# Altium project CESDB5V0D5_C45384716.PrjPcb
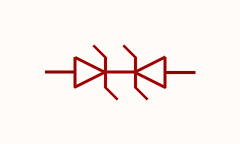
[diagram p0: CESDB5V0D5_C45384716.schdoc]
1 sheet, 1 parts. Net scope: global (net labels, ports and power ports of the same name join across sheets).

## Sheet CESDB5V0D5_C45384716.schdoc
size 127 x 101 mm

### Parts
D?  cesdb5v0d5_c45384716  [SOD-523_L1.2-W0.8-LS1.6-BI-1]  (value not drawn)

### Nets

Not connected (* = marked no-connect by the designer): D? 1 2

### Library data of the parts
D? = cesdb5v0d5_c45384716: 极性:双向;反向截止电压(Vrwm):5V;钳位电压:16V;峰值脉冲电流(Ipp):7A@8/20us;峰值脉冲功率(Ppp):100W@8/20us;击穿电压(VBR):8V;; Manufacturer: JSMSEMI(杰盛微); AddInBom: yes; ModelId: 1c16aded1c9949d28765d4c5d55c2785; ModelTransform: 62.992,31.496,0,0,0,0,0,0,0; Polarity: 双向; Reverse Stand-Off Voltage (Vrwm): 5V; Clamping Voltage: 16V; Voltage - Breakdown: 8V; Reverse Leakage Current (Ir): 51uA; Number of Channels: 单路; level of protection: IEC 61000-4-2; Type: TVS; Junction Capacitance: 12pF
